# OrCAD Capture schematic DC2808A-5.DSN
size Custom; company: ANALOG DEVICES; note: DEMO BOARD BILL OF MATERIALS; note: RECEIVER TIA 4:1
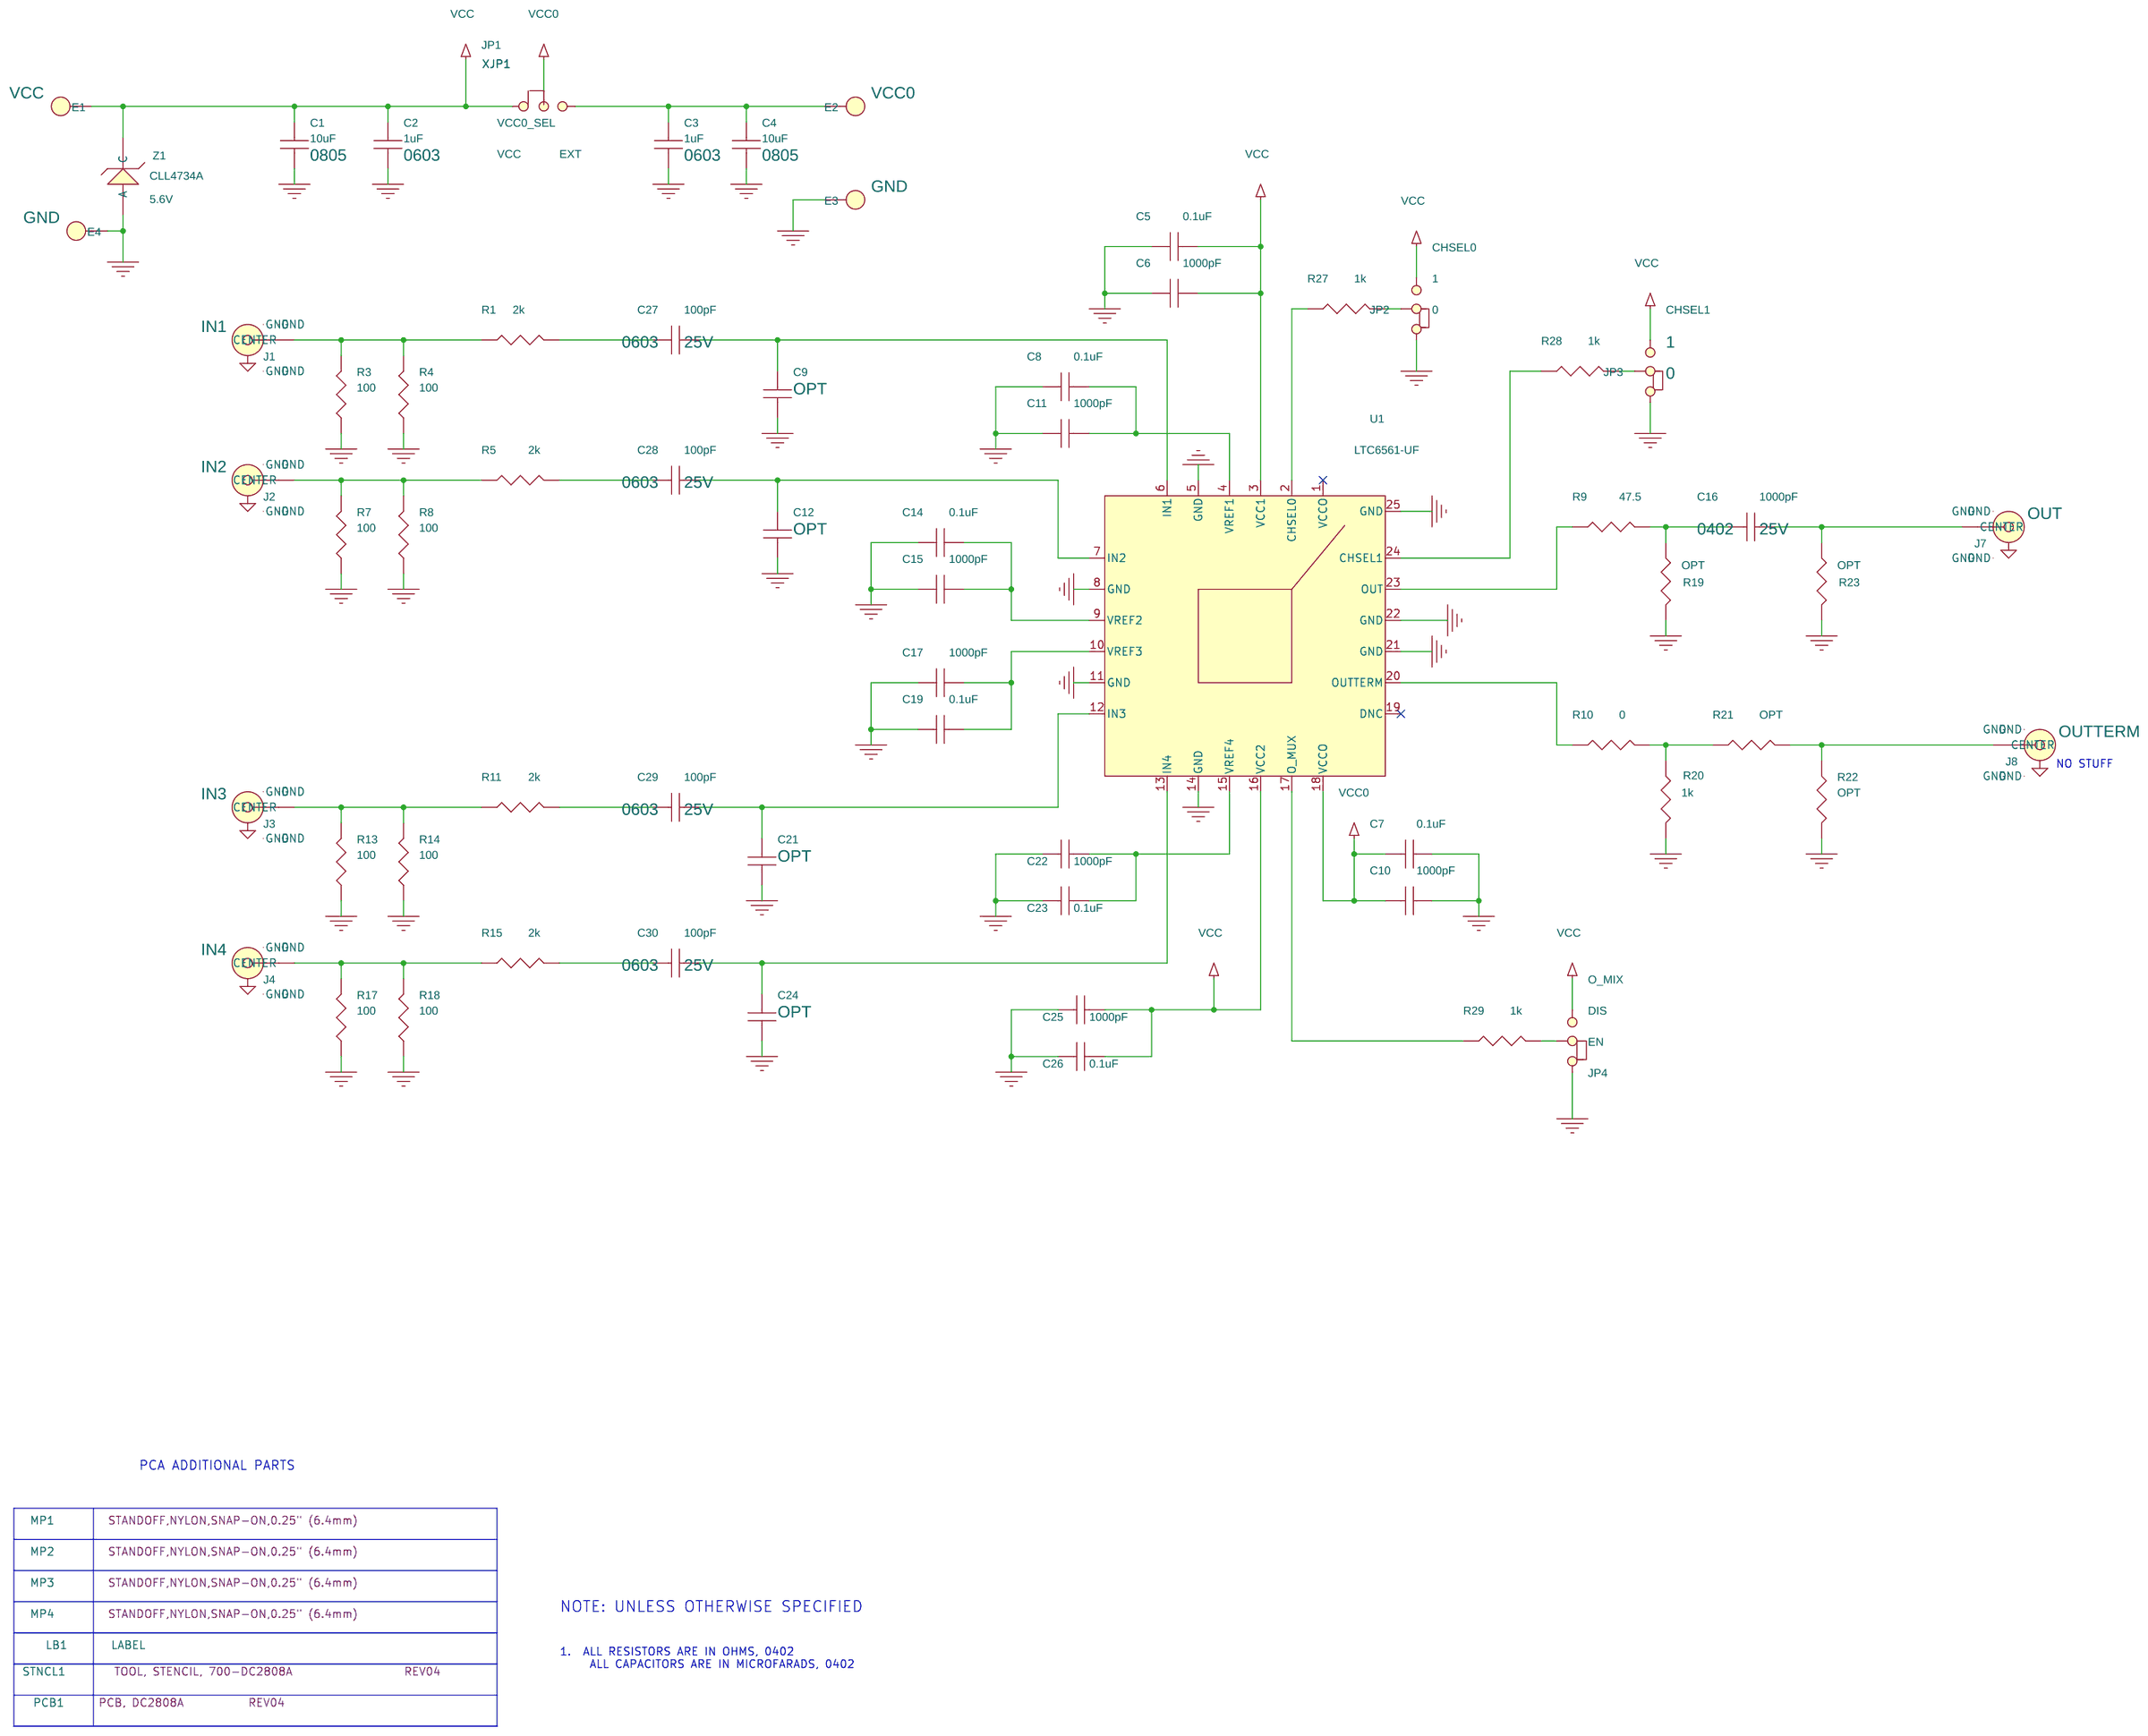
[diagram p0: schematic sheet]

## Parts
C1  10uF  [CC0805N]
C2  1uF  [CC0603N]
C3  1uF  [CC0603N]
C4  10uF  [CC0805N]
C5  0.1uF  [CC0603N]
C6  1000pF  [CC0402N]
C7  0.1uF  [CC0603N]
C8  0.1uF  [CC0603N]
C9  OPT  [CC0402N]
C10  1000pF  [CC0402N]
C11  1000pF  [CC0402N]
C12  OPT  [CC0402N]
C14  0.1uF  [CC0603N]
C15  1000pF  [CC0402N]
C16  1000pF  [CC0402N]
C17  1000pF  [CC0402N]
C19  0.1uF  [CC0603N]
C21  OPT  [CC0402N]
C22  1000pF  [CC0402N]
C23  0.1uF  [CC0603N]
C24  OPT  [CC0402N]
C25  1000pF  [CC0402N]
C26  0.1uF  [CC0603N]
C27  100pF  [CC0603N]
C28  100pF  [CC0603N]
C29  100pF  [CC0603N]
C30  100pF  [CC0603N]
E1  TEST POINT  [MILLMAX2308]
E2  TEST POINT  [MILLMAX2308]
E3  TEST POINT  [MILLMAX2308]
E4  TEST POINT  [MILLMAX2308]
J1  SMA  [EMERSON_142-0701-851]
J2  SMA  [EMERSON_142-0701-851]
J3  SMA  [EMERSON_142-0701-851]
J4  SMA  [EMERSON_142-0701-851]
J7  SMA  [EMERSON_142-0701-851]
J8  SMA  [EMERSON_142-0701-851]
JP1  HDR  [HD1X3-079]
JP2  HDR  [HD1X3-079]
JP3  HDR  [HD1X3-079]
JP4  HDR  [HD1X3-079]
LB1  LABEL  [895-0154_REV01]
MP1  STANDOFF  [MTG-8831]
MP2  STANDOFF  [MTG-8831]
MP3  STANDOFF  [MTG-8831]
MP4  STANDOFF  [MTG-8831]
PCB1  PCB, DC2808A
R1  2k  [CR0402N]
R3  100  [CR0402N]
R4  100  [CR0402N]
R5  2k  [CR0402N]
R7  100  [CR0402N]
R8  100  [CR0402N]
R9  47.5  [CR0402N]
R10  0  [CR0402N]
R11  2k  [CR0402N]
R13  100  [CR0402N]
R14  100  [CR0402N]
R15  2k  [CR0402N]
R17  100  [CR0402N]
R18  100  [CR0402N]
R19  OPT  [CR0402N]
R20  1k  [CR0402N]
R21  OPT  [CR0402N]
R22  OPT  [CR0402N]
R23  OPT  [CR0402N]
R27  1k  [CR0402N]
R28  1k  [CR0402N]
R29  1k  [CR0402N]
STNCL1  TOOL, STENCIL, 700-DC2808A
U1  LTC6561-UF  [LTC-UF-24-1697]
XJP1  JUMPER LINK  [PCBJUMPER_2POS]
XJP2  SHUNT
XJP3  SHUNT
XJP4  SHUNT
Z1  CLL4734A  [CENTRALSEMI-MELF]

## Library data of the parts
C1 C4 = CAP: CAP.,10uF,X5R,25V,10%,0805; CLASS: DISCRETE; Dielectric Type: X5R; FPLIST: CC0805N,CC0805L,CC0805M; Inventory Qty: 15793; Manufacturer: SAMSUNG; Manufacturer PN: CL21A106KAFN3NE; PART_NUMBER: 150-3405; Package Size: 0805; Package Type: SMD; Rated Voltage: 25V; Tolerance: 10%
C2 C3 = CAP: CAP.,1uF,X5R,50V,10%,0603; CLASS: DISCRETE; Dielectric Type: X5R; FPLIST: CC0603N,CC0603L,CC0603M; Inventory Qty: 12826; Manufacturer: AVX; Manufacturer PN: 06035D105KAT2A; PART_NUMBER: 150-3292; Package Size: 0603; Package Type: SMD; Rated Voltage: 50V; Tolerance: 10%
C5 C7 C8 C14 C19 C23 C26 = CAP: CAP.,0.1uF,X7R,50V,10%,0603; CLASS: DISCRETE; Dielectric Type: X7R; FPLIST: CC0603N,CC0603L,CC0603M; Inventory Qty: 101087; Manufacturer: AVX; Manufacturer PN: 06035C104KAT2A; PART_NUMBER: 150-3082; Package Size: 0603; Package Type: SMD; Rated Voltage: 50V; Tolerance: 10%
C6 C10 C11 C15 C17 C22 C25 = CAP: CAP.,1000pF,X7R,16V,10%,0402; CLASS: DISCRETE; Dielectric Type: X7R; FPLIST: CC0402N,CC0402L,CC0402M; Inventory Qty: 9944; Manufacturer: AVX; Manufacturer PN: 0402YC102KAT2A; PART_NUMBER: 150-3197; Package Size: 0402; Rated Voltage: 16V; Tolerance: 10%
C9 C12 C21 C24 = CAP: CAP., OPTION, 0402; 1: *; CLASS: DISCRETE; FPLIST: CC0402N,CC0402L,CC0402M; PART_NUMBER: 150-3148; Package Size: 0402; Package Type: SMD
C16 = CAP: CAP.,1000pF,X7R,25V,10%,0402; CLASS: DISCRETE; Dielectric Type: X7R; FPLIST: CC0402N,CC0402L,CC0402M; Inventory Qty: 28890; Manufacturer: AVX; Manufacturer PN: 04023C102KAT2A; PART_NUMBER: 150-2012; Package Size: 0402; Rated Voltage: 25V; Tolerance: 10%
C27-C30 = CAP: CAP.,100pF,C0G,25V,10%,0603; CLASS: DISCRETE; Dielectric Type: C0G; FPLIST: CC0603N,CC0603L,CC0603M; Inventory Qty: 33000; Manufacturer: AVX; Manufacturer PN: 06033A101KAT2A; PART_NUMBER: 150-3276; Package Size: 0603; Rated Voltage: 25V; Tolerance: 10%
E1 = TEST_POINT_.156_MILL-MAX_2308: TEST POINT,TURRET,0.064" MTG. HOLE,PCB 0.062" THICK; 1: VCC; CLASS: IO; Inventory Qty: 838135; Manufacturer: MILL-MAX; Manufacturer PN: 2308-2-00-80-00-00-07-0; PART_NUMBER: 260-0004
E2 = TEST_POINT_.156_MILL-MAX_2308: TEST POINT,TURRET,0.064" MTG. HOLE,PCB 0.062" THICK; 1: VCC0; CLASS: IO; Inventory Qty: 838135; Manufacturer: MILL-MAX; Manufacturer PN: 2308-2-00-80-00-00-07-0; PART_NUMBER: 260-0004
E3 E4 = TEST_POINT_.156_MILL-MAX_2308: TEST POINT,TURRET,0.064" MTG. HOLE,PCB 0.062" THICK; 1: GND; CLASS: IO; Inventory Qty: 838135; Manufacturer: MILL-MAX; Manufacturer PN: 2308-2-00-80-00-00-07-0; PART_NUMBER: 260-0004
J1 = CONN_SMA_5PIN: CONN.,SMA,JACK, RCPT,END LAUNCH, STR,50 OHMS; 1: IN1; BOM Notes: NO STUFF J8; CLASS: IO; FPLIST: EMERSON_142-0701-851,SMA-CINCH-142-0761-881_142-0701-851; Inventory Qty: 26352; Manufacturer: CINCH/ BEL; Manufacturer PN: 142-0701-851; PART_NUMBER: 250-0446
J2 = CONN_SMA_5PIN: CONN.,SMA,JACK, RCPT,END LAUNCH, STR,50 OHMS; 1: IN2; BOM Notes: NO STUFF J8; CLASS: IO; FPLIST: EMERSON_142-0701-851,SMA-CINCH-142-0761-881_142-0701-851; Inventory Qty: 26352; Manufacturer: CINCH/ BEL; Manufacturer PN: 142-0701-851; PART_NUMBER: 250-0446
J3 = CONN_SMA_5PIN: CONN.,SMA,JACK, RCPT,END LAUNCH, STR,50 OHMS; 1: IN3; BOM Notes: NO STUFF J8; CLASS: IO; FPLIST: EMERSON_142-0701-851,SMA-CINCH-142-0761-881_142-0701-851; Inventory Qty: 26352; Manufacturer: CINCH/ BEL; Manufacturer PN: 142-0701-851; PART_NUMBER: 250-0446
J4 = CONN_SMA_5PIN: CONN.,SMA,JACK, RCPT,END LAUNCH, STR,50 OHMS; 1: IN4; BOM Notes: NO STUFF J8; CLASS: IO; FPLIST: EMERSON_142-0701-851,SMA-CINCH-142-0761-881_142-0701-851; Inventory Qty: 26352; Manufacturer: CINCH/ BEL; Manufacturer PN: 142-0701-851; PART_NUMBER: 250-0446
J7 = CONN_SMA_5PIN: CONN.,SMA,JACK, RCPT,END LAUNCH, STR,50 OHMS; 1: OUT; BOM Notes: NO STUFF J8; CLASS: IO; FPLIST: EMERSON_142-0701-851,SMA-CINCH-142-0761-881_142-0701-851; Inventory Qty: 26352; Manufacturer: CINCH/ BEL; Manufacturer PN: 142-0701-851; PART_NUMBER: 250-0446
J8 = CONN_SMA_5PIN: CONN.,SMA,JACK, RCPT,END LAUNCH, STR,50 OHMS; 1: OUTTERM; BOM Notes: NO STUFF J8; CLASS: IO; FPLIST: EMERSON_142-0701-851,SMA-CINCH-142-0761-881_142-0701-851; Inventory Qty: 26352; Manufacturer: CINCH/ BEL; Manufacturer PN: 142-0701-851; PART_NUMBER: 250-0446
JP1 = 3_PIN_HEADER_.079_SINGLE_ROW: CONN.,HDR,MALE,1x3,2mm,VERT,STR,THT; 1: VCC0_SEL; 2: VCC; 3: EXT; BOM Notes: NO STUFF JP1; CLASS: IO; Inventory Qty: 29697; Manufacturer: Wurth Elektronik; Manufacturer PN: 62000311121; PART_NUMBER: 250-0484
JP2 = 3_PIN_HEADER_.079_SINGLE_ROW: CONN.,HDR,MALE,1x3,2mm,VERT,STR,THT; 1: CHSEL0; 2: 1; 3: 0; BOM Notes: NO STUFF JP1; CLASS: IO; Inventory Qty: 29697; Manufacturer: Wurth Elektronik; Manufacturer PN: 62000311121; PART_NUMBER: 250-0484
JP3 = 3_PIN_HEADER_.079_SINGLE_ROW: CONN.,HDR,MALE,1x3,2mm,VERT,STR,THT; 1: CHSEL1; 2: 1; 3: 0; BOM Notes: NO STUFF JP1; CLASS: IO; Inventory Qty: 29697; Manufacturer: Wurth Elektronik; Manufacturer PN: 62000311121; PART_NUMBER: 250-0484
JP4 = 3_PIN_HEADER_.079_SINGLE_ROW: CONN.,HDR,MALE,1x3,2mm,VERT,STR,THT; 1: O_MIX; 2: DIS; 3: EN; BOM Notes: NO STUFF JP1; CLASS: IO; Inventory Qty: 29697; Manufacturer: Wurth Elektronik; Manufacturer PN: 62000311121; PART_NUMBER: 250-0484
LB1 = BLANK_LABEL: LABEL SPEC, DEMO BOARD SERIAL NUMBER; Inventory Qty: 0; Manufacturer: BRADY; Manufacturer PN: THT-96-717-10; PART_NUMBER: 895-0154
MP1-MP4 = BLANK_MECHANICAL_PART: STANDOFF,NYLON,SNAP-ON,0.25" (6.4mm); CLASS: MECHANICAL PART; Inventory Qty: 190808; Manufacturer: KEYSTONE; Manufacturer PN: 8831; PART_NUMBER: 763-0006
PCB1 = BLANK_PCB_PART: BOM Notes: REV04; CLASS: DISCRETE; Inventory Qty: 0; Manufacturer: EAGLE TECH. INC.; Manufacturer PN: 600-DC2808A; PART_NUMBER: 600-DC2808A
R1 R5 R11 R15 = RES: RES.,2k OHMS,1%,1/16W,0402,AEC-Q200; 1: *; CLASS: DISCRETE; FPLIST: CR0402N,CR0402L,CR0402M; Inventory Qty: 34486; Manufacturer: VISHAY; Manufacturer PN: CRCW04022K00FKED; PART_NUMBER: 100-0018; Package Size: 0402; Rated Power: 1/16W; Temperature Coefficient: 100ppm/C; Tolerance: 1%
R3 R4 R7 R8 R13 R14 R17 R18 = RES: RES.,100 OHMS,1%,1/16W,0402; 1: *; CLASS: DISCRETE; FPLIST: CR0402N,CR0402L,CR0402M; Inventory Qty: 48112; Manufacturer: NIC; Manufacturer PN: NRC04F1000TRF; PART_NUMBER: 100-2626; Package Size: 0402; Rated Power: 1/16W; Temperature Coefficient: 100ppm/C; Tolerance: 1%
R9 = RES: RES.,47.5 OHMS,1%,1/16W,0402,AEC-Q200; CLASS: DISCRETE; FPLIST: CR0402N,CR0402L,CR0402M; Inventory Qty: 16621; Manufacturer: STACKPOLE ELECTRONICS; Manufacturer PN: RMCF0402FT47R5; PART_NUMBER: 100-1002; Package Size: 0402; Rated Power: 1/16W; Temperature Coefficient: 100ppm; Tolerance: 1%
R10 = RES: RES.,0 OHM,1/16W,0402; CLASS: DISCRETE; FPLIST: CR0402N,CR0402L,CR0402M; Inventory Qty: 56202; Manufacturer: NIC; Manufacturer PN: NRC04ZOTRF; PART_NUMBER: 100-0025; Package Size: 0402; Rated Power: 1/16W
R19 R21-R23 = RES: RES., OPTION, 0402; CLASS: DISCRETE; FPLIST: CR0402N,CR0402L,CR0402M; PART_NUMBER: 100-0357; Package Size: 0402
R20 R27-R29 = RES: RES.,1k OHM,1%,1/16W,0402,AEC-Q200; CLASS: DISCRETE; FPLIST: CR0402N,CR0402L,CR0402M; Inventory Qty: 114668; Manufacturer: VISHAY; Manufacturer PN: CRCW04021K00FKED; PART_NUMBER: 100-2456; Package Size: 0402; Rated Power: 1/16W; Temperature Coefficient: 100ppm/C; Tolerance: 1%
STNCL1 = BLANK_STENCIL_PART: BOM Notes: REV04; CLASS: DISCRETE; Inventory Qty: 0; Manufacturer: LINEAR TECH.; Manufacturer PN: 830-DC2808A; PART_NUMBER: 830-DC2808A
U1 = LTC6561-UF: IC,4-Channel Multiplexed TIA,QFN-24 (4x4); CLASS: IC; Inventory Qty: 0; Manufacturer: LINEAR TECH.; Manufacturer PN: LTC6561HUF#PBF; PART_NUMBER: LTC6561HUF#PBF; Package Type: QFN-24 (4x4)
XJP1 = SHNT_A: CONN.,JUMPER LINK,MALE,1x2,2.54mm,THT,WHITE INSULATED; CLASS: IO; Inventory Qty: 3780; Manufacturer: SAMTEC; Manufacturer PN: JL-100-25-T; PART_NUMBER: 250-0448
XJP2-XJP4 = SHUNT_2MM_B: CONN.,SHUNT,FEMALE,2-POS,2mm; CLASS: IO; Inventory Qty: 72074; Manufacturer: SAMTEC; Manufacturer PN: 2SN-BK-G; PART_NUMBER: 250-0419
Z1 = ZENER: DIODE,ZENER,5.6V,1W,MELF; CLASS: DISCRETE; Inventory Qty: 1000; Manufacturer: CENTRAL SEMI.; Manufacturer PN: CLL4734A TR PBFREE; Max Forward Current or Rated Power: 810mW; PART_NUMBER: 210-0336; Package Type: MELF; Rated Voltage: 5.6V; Rated Voltage or Zener Voltage: 5.6V

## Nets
GND: C1.2 C2.2 C3.2 C4.2 C5.1 C6.1 C7.1 C8.1 C9.2 C10.1 C11.1 C12.2 C14.1 C15.1 C17.1 C19.1 C21.2 C22.1 C23.1 C24.2 C25.1 C26.1 E3.1(A) E4.1(A) J1.2(GND) J1.3(GND) J1.4(GND) J1.5(GND) J2.2(GND) J2.3(GND) J2.4(GND) J2.5(GND) J3.2(GND) J3.3(GND) J3.4(GND) J3.5(GND) J4.2(GND) J4.3(GND) J4.4(GND) J4.5(GND) J7.2(GND) J7.3(GND) J7.4(GND) J7.5(GND) J8.2(GND) J8.3(GND) J8.4(GND) J8.5(GND) JP2.3 JP3.3 JP4.3 R3.1 R4.1 R7.1 R8.1 R13.1 R14.1 R17.1 R18.1 R19.1 R20.2 R22.2 R23.1 U1.5(GND) U1.8(GND) U1.11(GND) U1.14(GND) U1.21(GND) U1.22(GND) U1.25(GND) Z1.2(A)
VCC: C1.1 C2.1 C5.2 C6.2 C25.2 C26.2 E1.1(A) JP1.3 JP2.1 JP3.1 JP4.1 U1.3(VCC1) U1.16(VCC2) Z1.1(C)
VCC0: C7.2 C10.2 JP1.2 U1.18(VCCO)
N17311466: J1.1(CENTER) R1.1 R3.2 R4.2
N17311531: C27.1 R1.2
N17311537: C9.1 C27.2 U1.6(IN1)
N17312116: J2.1(CENTER) R5.1 R7.2 R8.2
N17312126: C28.1 R5.2
N17312130: C12.1 C28.2 U1.7(IN2)
N17312299: J3.1(CENTER) R11.1 R13.2 R14.2
N17312309: C29.1 R11.2
N17312313: C21.1 C29.2 U1.12(IN3)
N17312485: J4.1(CENTER) R15.1 R17.2 R18.2
N17312495: C30.1 R15.2
N17312499: C24.1 C30.2 U1.13(IN4)
N17312893: C14.2 C15.2 U1.9(VREF2)
N17312998: C17.2 C19.2 U1.10(VREF3)
N17313800: C8.2 C11.2 U1.4(VREF1)
N17313910: C22.2 C23.2 U1.15(VREF4)
N17315718: R29.1 U1.17(O_MUX)
N17318352: R28.1 U1.24(CHSEL1)
N17319555: R9.1 U1.23(OUT)
N17319584: R10.1 U1.20(OUTTERM)
N17319817: R10.2 R20.1 R21.1
N17319820: C16.2 J7.1(CENTER) R23.2
N17319827: J8.1(CENTER) R21.2 R22.1
N17326142: C3.1 C4.1 E2.1(A) JP1.1
N17342992: C16.1 R9.2 R19.2
N17349543: R27.1 U1.2(CHSEL0)
N17353156: JP2.2 R27.2
N17354012: JP3.2 R28.2
N17354362: JP4.2 R29.2

Not connected (* = marked no-connect by the designer): U1 1(VCCO)* 19(DNC)*

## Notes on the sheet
- NO STUFF
- PCA ADDITIONAL PARTS
- NOTE: UNLESS OTHERWISE SPECIFIED
- 1.  ALL RESISTORS ARE IN OHMS, 0402
       ALL CAPACITORS ARE IN MICROFARADS, 0402
